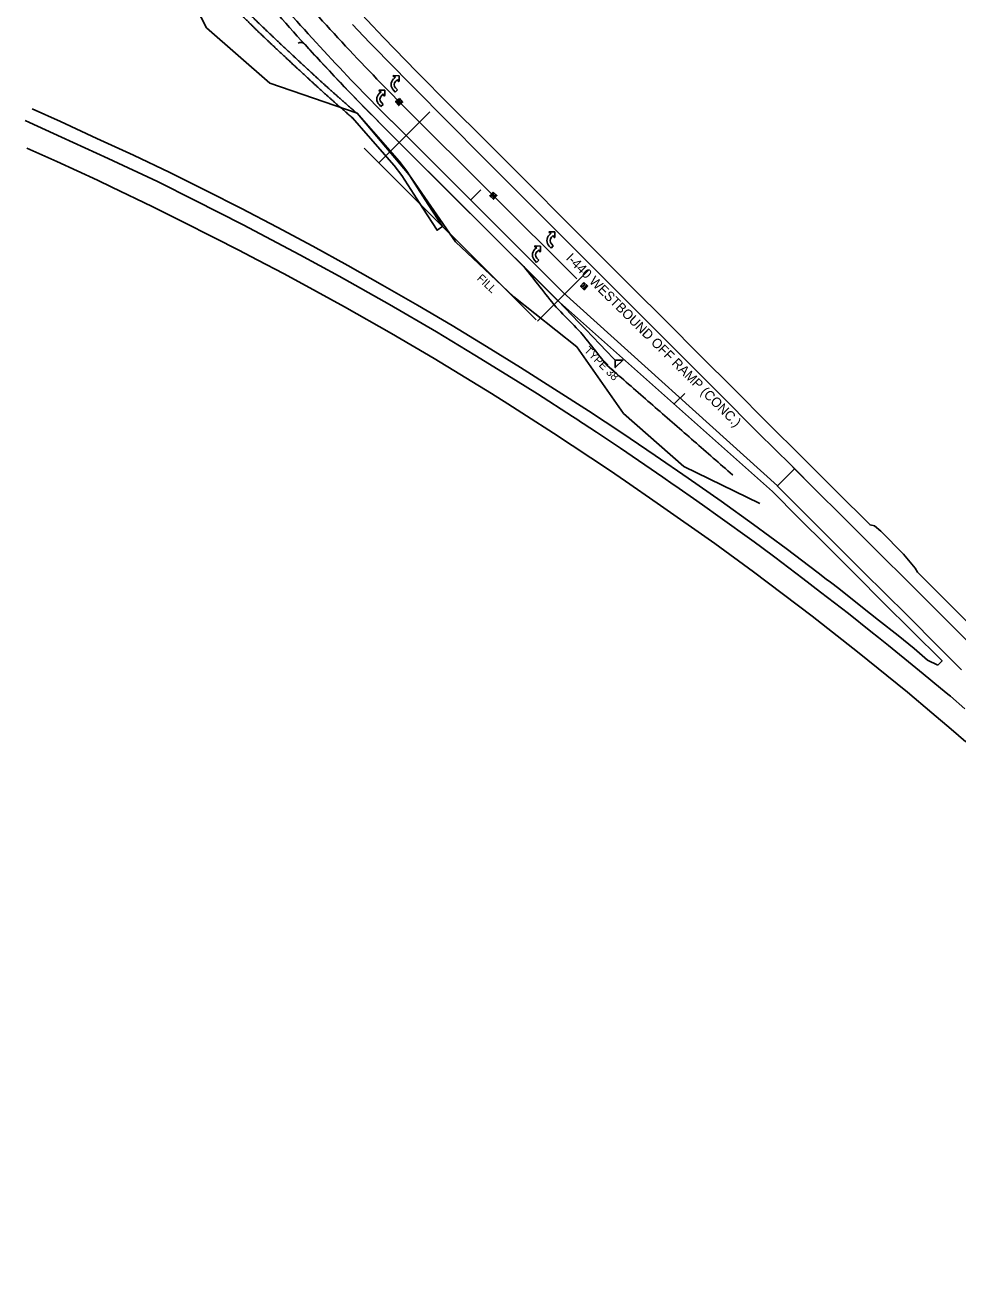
# Model space of a CAD drawing. Extents: x 1730210 to 1732101, y 650763 to 653427.
# Drawn here: x 1730478 to 1731060, y 651820 to 652609 of the extents above; entities that cross this region are included whole.
import ezdxf

# ---------------------------------------------------------------- set-up
doc = ezdxf.new("R2010")
doc.units = 0
for name, color, linetype in [('DESIGN - DRAINAGE - Special Ditches', 7, 'Continuous'), ('DESIGN - ROW - Slope Lines', 7, 'Continuous'), ('DESIGN - ROW - Slope Lines Text', 7, 'Continuous'), ('DESIGN - SCRATCH - User 1', 7, 'Continuous'), ('DESIGN - SCRATCH - User 2', 7, 'Continuous'), ('DESIGN - TRAFFIC CONTROL PERMANENT - Pavement Marking', 7, 'Continuous'), ('DESIGN - TRANSPORTATION - Edge of Traveled Way', 7, 'Continuous'), ('DESIGN - TRANSPORTATION - GR Special Slope Limit Lines', 7, 'Continuous'), ('DESIGN - TRANSPORTATION - Intersection Lines', 7, 'Continuous'), ('DESIGN - TRANSPORTATION - Roadside Barriers', 7, 'Continuous'), ('DESIGN - TRANSPORTATION - Shoulder Lines', 7, 'Continuous'), ('DESIGN - TRANSPORTATION - Text', 7, 'Continuous'), ('FUNCTIONAL - TRANSPORTATION - Preliminary Edge of Traveled Way', 7, 'Continuous'), ('SURVEY - DRAINAGE - Pipes and Culverts', 7, 'Continuous'), ('SURVEY - TRANSPORTATION - Features', 7, 'Continuous'), ('SURVEY - TRANSPORTATION - Roads', 7, 'Continuous'), ('SURVEY - TRANSPORTATION - Roads Text', 7, 'Continuous')]:
    doc.layers.add(name, color=color, linetype=linetype)

msp = doc.modelspace()

# ---------------------------------------------------------------- linework, layer by layer
at = {"layer": 'DESIGN - DRAINAGE - Special Ditches'}
msp.add_line((1730644.22, 652585.3), (1730644.22, 652585.3), dxfattribs=at)
for points in [[(1730610.11, 652623.81), (1730622.09, 652611.66), (1730634.46, 652599.88), (1730646.95, 652588.22)], [(1730607.26, 652621), (1730619.3, 652608.79), (1730631.71, 652596.98), (1730644.22, 652585.3)], [(1730644.22, 652585.3), (1730656.67, 652573.69), (1730669.31, 652562.29), (1730682.13, 652551.09)], [(1730646.95, 652588.22), (1730659.36, 652576.64), (1730671.97, 652565.27), (1730684.76, 652554.11)]]:
    msp.add_open_spline(points, degree=2, dxfattribs=at)
at = {"layer": 'DESIGN - ROW - Slope Lines'}
for p, q in [((1730565.43, 652657.01), (1730591, 652607.46)), ((1730591, 652607.46), (1730630.39, 652572.86)), ((1730630.39, 652572.86), (1730685.01, 652554.13)), ((1730685.01, 652554.13), (1730717.52, 652515.57)), ((1730717.52, 652515.57), (1730746.42, 652473.75)), ((1730746.42, 652473.75), (1730782.85, 652439.46)), ((1730782.85, 652439.46), (1730822.18, 652408.1)), ((1730822.18, 652408.1), (1730851.29, 652366.48)), ((1730851.29, 652366.48), (1730889.03, 652333.52)), ((1730889.03, 652333.52), (1730936.56, 652310.36))]:
    msp.add_line(p, q, dxfattribs=at)
at = {"layer": 'DESIGN - SCRATCH - User 1'}
for p, q in [((1730698.65, 652523.04), (1730730.44, 652554.89)), ((1730689.43, 652532.24), (1730796.78, 652425.11)), ((1730797.75, 652424.14), (1730829.53, 652456))]:
    msp.add_line(p, q, dxfattribs=at)
at = {"layer": 'DESIGN - SCRATCH - User 2'}
msp.add_lwpolyline([(1730682.18, 652609.42), (1730689.03, 652602.15), (1730693.2, 652597.85), (1730708.56, 652582.15), (1730715.58, 652575.04), (1730746.5, 652543.82), (1730759.18, 652531.06), (1730771.86, 652518.31), (1730793.02, 652497.08), (1730805.72, 652484.34), (1730831.15, 652458.88), (1730843.88, 652446.17), (1730863.71, 652426.41), (1730875.03, 652415.1), (1730899.04, 652391.04), (1730910.37, 652379.75), (1730935.76, 652354.33), (1730956.03, 652334.21), (1730971.98, 652318.3), (1730987.47, 652302.85), (1731007.33, 652283.11), (1731032.83, 652257.7), (1731045.57, 652244.98), (1731076.7, 652213.89)], dxfattribs=at)
at = {"layer": 'DESIGN - TRAFFIC CONTROL PERMANENT - Pavement Marking'}
for p, q in [((1730708.87, 652576.6), (1730707.71, 652575.46)), ((1730707.71, 652575.46), (1730708.87, 652576.6)), ((1730707.73, 652577.08), (1730708.87, 652576.6)), ((1730708.87, 652576.6), (1730707.73, 652577.08)), ((1730711.21, 652577.53), (1730707.83, 652577.55)), ((1730711.21, 652577.53), (1730707.83, 652577.55)), ((1730709.09, 652574.06), (1730710.25, 652575.2)), ((1730709.09, 652574.06), (1730710.25, 652575.2)), ((1730710.25, 652575.2), (1730710.71, 652574.06)), ((1730710.25, 652575.2), (1730710.71, 652574.06)), ((1730711.18, 652574.15), (1730711.21, 652577.53)), ((1730711.21, 652577.53), (1730711.18, 652574.15)), ((1730699.93, 652567.53), (1730698.77, 652566.39)), ((1730698.77, 652566.39), (1730699.93, 652567.53)), ((1730698.79, 652568.01), (1730699.93, 652567.53)), ((1730699.93, 652567.53), (1730698.79, 652568.01)), ((1730702.27, 652568.46), (1730698.89, 652568.48)), ((1730702.27, 652568.46), (1730698.89, 652568.48)), ((1730700.16, 652564.99), (1730701.31, 652566.13)), ((1730700.16, 652564.99), (1730701.31, 652566.13)), ((1730701.31, 652566.13), (1730701.77, 652564.99)), ((1730701.31, 652566.13), (1730701.77, 652564.99)), ((1730702.24, 652565.08), (1730702.27, 652568.46)), ((1730702.27, 652568.46), (1730702.24, 652565.08)), ((1730707.66, 652568.51), (1730708.84, 652567.31)), ((1730708.84, 652567.31), (1730707.66, 652568.51)), ((1730708.84, 652567.31), (1730710.24, 652568.69)), ((1730710.24, 652568.69), (1730708.84, 652567.31)), ((1730710.24, 652568.69), (1730709.06, 652569.89)), ((1730710.24, 652568.69), (1730709.06, 652569.89)), ((1730698.72, 652559.44), (1730699.9, 652558.24)), ((1730699.9, 652558.24), (1730698.72, 652559.44)), ((1730699.9, 652558.24), (1730701.3, 652559.62)), ((1730701.3, 652559.62), (1730699.9, 652558.24)), ((1730701.3, 652559.62), (1730700.12, 652560.82)), ((1730701.3, 652559.62), (1730700.12, 652560.82)), ((1730714.85, 652557.73), (1730822.21, 652450.59)), ((1730806.16, 652479.12), (1730805.01, 652477.99)), ((1730805.01, 652477.99), (1730806.16, 652479.12)), ((1730805.03, 652479.6), (1730806.16, 652479.12)), ((1730806.16, 652479.12), (1730805.03, 652479.6)), ((1730808.5, 652480.05), (1730805.12, 652480.07)), ((1730808.5, 652480.05), (1730805.12, 652480.07)), ((1730808.48, 652476.67), (1730808.5, 652480.05)), ((1730808.5, 652480.05), (1730808.48, 652476.67)), ((1730799.49, 652471.14), (1730796.11, 652471.17)), ((1730799.49, 652471.14), (1730796.11, 652471.17)), ((1730799.46, 652467.77), (1730799.49, 652471.14)), ((1730799.49, 652471.14), (1730799.46, 652467.77)), ((1730806.13, 652469.83), (1730807.53, 652471.22)), ((1730807.53, 652471.22), (1730806.13, 652469.83)), ((1730807.53, 652471.22), (1730806.36, 652472.41)), ((1730807.53, 652471.22), (1730806.36, 652472.41)), ((1730806.39, 652476.58), (1730807.54, 652477.72)), ((1730806.39, 652476.58), (1730807.54, 652477.72)), ((1730807.54, 652477.72), (1730808, 652476.58)), ((1730807.54, 652477.72), (1730808, 652476.58)), ((1730797.14, 652470.22), (1730795.99, 652469.08)), ((1730795.99, 652469.08), (1730797.14, 652470.22)), ((1730796.01, 652470.7), (1730797.14, 652470.22)), ((1730797.14, 652470.22), (1730796.01, 652470.7)), ((1730798.52, 652462.31), (1730797.34, 652463.51)), ((1730798.52, 652462.31), (1730797.34, 652463.51)), ((1730797.37, 652467.68), (1730798.52, 652468.82)), ((1730797.37, 652467.68), (1730798.52, 652468.82)), ((1730798.52, 652468.82), (1730798.99, 652467.68)), ((1730798.52, 652468.82), (1730798.99, 652467.68)), ((1730804.95, 652471.03), (1730806.13, 652469.83)), ((1730806.13, 652469.83), (1730804.95, 652471.03)), ((1730795.94, 652462.13), (1730797.12, 652460.93)), ((1730797.12, 652460.93), (1730795.94, 652462.13)), ((1730797.12, 652460.93), (1730798.52, 652462.31)), ((1730798.52, 652462.31), (1730797.12, 652460.93))]:
    msp.add_line(p, q, dxfattribs=at)
for points in [[(1730711.39, 652563.3), (1730708.98, 652561.26), (1730711.02, 652558.86), (1730713.42, 652560.9), (1730711.39, 652563.3)], [(1730711.39, 652563.3), (1730711.27, 652561.89), (1730710.36, 652561.11), (1730708.98, 652561.26)], [(1730713.42, 652560.9), (1730712.01, 652561.01), (1730711.1, 652560.23), (1730711.02, 652558.86)], [(1730770.01, 652504.8), (1730767.86, 652502.49), (1730770.16, 652500.34), (1730772.31, 652502.65), (1730770.01, 652504.8)], [(1730770.01, 652504.8), (1730770.06, 652503.38), (1730769.24, 652502.51), (1730767.86, 652502.49)], [(1730772.31, 652502.65), (1730770.9, 652502.6), (1730770.08, 652501.72), (1730770.16, 652500.34)], [(1730826.67, 652448.32), (1730824.52, 652446.01), (1730826.82, 652443.86), (1730828.97, 652446.17), (1730826.67, 652448.32)], [(1730826.67, 652448.32), (1730826.72, 652446.9), (1730825.9, 652446.03), (1730824.52, 652446.01)], [(1730828.97, 652446.17), (1730827.56, 652446.12), (1730826.74, 652445.24), (1730826.82, 652443.86)]]:
    msp.add_lwpolyline(points, dxfattribs=at)
for points in [[(1730711.27, 652561.89), (1730712.01, 652561.01), (1730711.1, 652560.23), (1730710.36, 652561.11)], [(1730770.06, 652503.38), (1730770.9, 652502.6), (1730770.08, 652501.72), (1730769.24, 652502.51)], [(1730826.72, 652446.9), (1730827.56, 652446.12), (1730826.74, 652445.24), (1730825.9, 652446.03)]]:
    msp.add_lwpolyline(points, close=True, dxfattribs=at)
for centre, radius, start, end in [((1731772.3, 653617.35), 1497, 220.70969, 225.05905), ((1730711.17, 652571.96), 4.92, 134.56927, 224.56927), ((1730711.17, 652571.96), 4.92, 134.56927, 224.56927), ((1730707.83, 652577.3), 0.246, 89.56927, 247.01753), ((1730707.83, 652577.3), 0.246, 89.56927, 247.01753), ((1730711.17, 652571.96), 2.95, 134.56927, 224.56927), ((1730711.17, 652571.96), 2.95, 134.56927, 224.56927), ((1730710.94, 652574.15), 0.246, 202.07611, 359.56927), ((1730710.94, 652574.15), 0.246, 202.07611, 359.56927), ((1730702.23, 652562.89), 4.92, 134.56927, 224.56927), ((1730702.23, 652562.89), 4.92, 134.56927, 224.56927), ((1730698.89, 652568.23), 0.246, 89.56927, 247.01753), ((1730698.89, 652568.23), 0.246, 89.56927, 247.01753), ((1730702.23, 652562.89), 2.95, 134.56927, 224.56927), ((1730702.23, 652562.89), 2.95, 134.56927, 224.56927), ((1730702, 652565.08), 0.246, 202.07611, 359.56927), ((1730702, 652565.08), 0.246, 202.07611, 359.56927), ((1730805.12, 652479.83), 0.246, 89.56927, 247.01753), ((1730805.12, 652479.83), 0.246, 89.56927, 247.01753), ((1730796.11, 652470.92), 0.246, 89.56927, 247.01753), ((1730796.11, 652470.92), 0.246, 89.56927, 247.01753), ((1730808.46, 652474.48), 4.92, 134.56927, 224.56927), ((1730808.46, 652474.48), 4.92, 134.56927, 224.56927), ((1730808.46, 652474.48), 2.95, 134.56927, 224.56927), ((1730808.46, 652474.48), 2.95, 134.56927, 224.56927), ((1730808.23, 652476.67), 0.246, 202.07611, 359.56927), ((1730808.23, 652476.67), 0.246, 202.07611, 359.56927), ((1730799.44, 652465.58), 4.92, 134.56927, 224.56927), ((1730799.44, 652465.58), 4.92, 134.56927, 224.56927), ((1730799.44, 652465.58), 2.95, 134.56927, 224.56927), ((1730799.44, 652465.58), 2.95, 134.56927, 224.56927), ((1730799.21, 652467.77), 0.246, 202.07611, 359.56927), ((1730799.21, 652467.77), 0.246, 202.07611, 359.56927)]:
    msp.add_arc(centre, radius, start, end, dxfattribs=at)
at = {"layer": 'DESIGN - TRANSPORTATION - Edge of Traveled Way'}
for p in [(1730706.38, 652549.23), (1730947.5, 652321.32)]:
    msp.add_line(p, (1730813.73, 652442.1), dxfattribs=at)
msp.add_lwpolyline([(1730682.18, 652609.42), (1730689.03, 652602.15), (1730693.2, 652597.85), (1730708.56, 652582.15), (1730715.58, 652575.04), (1730746.5, 652543.82), (1730759.18, 652531.06), (1730771.86, 652518.31), (1730793.02, 652497.08), (1730805.72, 652484.34), (1730831.15, 652458.88), (1730843.88, 652446.17), (1730863.71, 652426.41), (1730875.03, 652415.1), (1730899.04, 652391.04), (1730910.37, 652379.75), (1730935.76, 652354.33), (1730956.03, 652334.21), (1730958.2, 652332.05)], dxfattribs=at)
msp.add_arc((1731772.3, 653617.35), 1509, 220.70969, 225.05905, dxfattribs=at)
at = {"layer": 'DESIGN - TRANSPORTATION - GR Special Slope Limit Lines'}
msp.add_lwpolyline([(1730789.07, 652458.32), (1730790.32, 652456.74), (1730791.57, 652455.16), (1730792.82, 652453.58), (1730794.07, 652452), (1730795.32, 652450.42), (1730796.57, 652448.84), (1730797.82, 652447.26), (1730799.07, 652445.68), (1730800.32, 652444.11), (1730801.56, 652442.53), (1730802.81, 652440.95), (1730804.06, 652439.37), (1730805.31, 652437.79), (1730806.56, 652436.21), (1730807.81, 652434.63), (1730807.99, 652434.41), (1730809.38, 652432.97), (1730810.76, 652431.53), (1730812.15, 652430.08), (1730813.54, 652428.64), (1730814.93, 652427.2), (1730816.31, 652425.76), (1730817.7, 652424.32), (1730819.09, 652422.88), (1730820.47, 652421.44), (1730821.86, 652420), (1730823.25, 652418.56), (1730824.64, 652417.11), (1730825.33, 652416.39), (1730826.58, 652414.82), (1730827.84, 652413.24), (1730829.09, 652411.67), (1730830.34, 652410.09), (1730831.6, 652408.52), (1730832.85, 652406.94), (1730834.1, 652405.37), (1730835.36, 652403.79), (1730836.61, 652402.21), (1730837.86, 652400.64), (1730839.12, 652399.06), (1730840.37, 652397.49), (1730841, 652396.7), (1730842.51, 652395.38), (1730844.02, 652394.06), (1730845.53, 652392.74), (1730847.04, 652391.43), (1730848.54, 652390.11), (1730850.05, 652388.79), (1730851.56, 652387.47), (1730853.07, 652386.15), (1730854.58, 652384.83), (1730856.09, 652383.52), (1730857.6, 652382.2), (1730859.11, 652380.88), (1730860.62, 652379.56), (1730862.13, 652378.24), (1730863.64, 652376.92), (1730865.15, 652375.61), (1730866.66, 652374.29), (1730868.17, 652372.97), (1730869.68, 652371.65), (1730871.19, 652370.33), (1730872.7, 652369.01), (1730874.21, 652367.7), (1730875.72, 652366.38), (1730877.23, 652365.06), (1730878.74, 652363.74), (1730880.25, 652362.42), (1730881.76, 652361.1), (1730883.27, 652359.79), (1730884.78, 652358.47), (1730886.29, 652357.15), (1730887.8, 652355.83), (1730889.31, 652354.51), (1730890.82, 652353.19), (1730892.33, 652351.87), (1730893.84, 652350.56), (1730895.35, 652349.24), (1730896.86, 652347.92), (1730898.37, 652346.6), (1730899.88, 652345.28), (1730901.39, 652343.96), (1730902.9, 652342.65), (1730904.41, 652341.33), (1730905.92, 652340.01), (1730907.43, 652338.69), (1730908.94, 652337.37), (1730910.45, 652336.05), (1730911.96, 652334.74), (1730913.47, 652333.42), (1730914.98, 652332.1), (1730916.49, 652330.78), (1730918, 652329.46), (1730919.51, 652328.14), (1730919.56, 652328.1)], dxfattribs=at)
at = {"layer": 'DESIGN - TRANSPORTATION - Intersection Lines'}
msp.add_line((1730947.5, 652321.32), (1730958.2, 652332.05), dxfattribs=at)
at = {"layer": 'DESIGN - TRANSPORTATION - Roadside Barriers'}
for p, q in [((1730810.46, 652436.89), (1730702.14, 652544.98)), ((1730846.23, 652399.82), (1730845.19, 652400.9))]:
    msp.add_line(p, q, dxfattribs=at)
msp.add_lwpolyline([(1730845.19, 652400.9), (1730840.85, 652405.41), (1730836.52, 652409.91), (1730832.18, 652414.41), (1730827.85, 652418.92), (1730823.51, 652423.42), (1730810.5, 652436.93)], dxfattribs=at)
msp.add_lwpolyline([(1730846.23, 652399.82), (1730846.21, 652395.23), (1730850.97, 652399.8)], close=True, dxfattribs=at)
for centre, radius, start, end in [((1730649.95, 652595.31), 3, 35.18125, 125.18125), ((1731772.3, 653617.35), 1515, 222.33605, 225.05905)]:
    msp.add_arc(centre, radius, start, end, dxfattribs=at)
at = {"layer": 'DESIGN - TRANSPORTATION - Shoulder Lines'}
for p in [(1730702.14, 652544.98), (1730944.36, 652317.85)]:
    msp.add_line(p, (1730809.6, 652437.75), dxfattribs=at)
msp.add_arc((1731772.3, 653617.35), 1515, 220.70969, 225.05905, dxfattribs=at)
at = {"layer": 'FUNCTIONAL - TRANSPORTATION - Preliminary Edge of Traveled Way'}
for p, q in [((1730762.24, 652506.2), (1730755.88, 652499.83)), ((1730889.65, 652379.05), (1730883.29, 652372.68))]:
    msp.add_line(p, q, dxfattribs=at)
at = {"layer": 'SURVEY - DRAINAGE - Pipes and Culverts'}
for points in [[(1730682.21, 652551.17), (1730691.97, 652539.87), (1730708.12, 652521.5), (1730712.97, 652515.27), (1730725.95, 652494.83), (1730734.99, 652480.99), (1730736.55, 652482.03), (1730738.37, 652483.24)], [(1730684.91, 652554.24), (1730694.97, 652542.61), (1730711.29, 652524.04), (1730716.13, 652517.81), (1730729.33, 652497.08), (1730738.37, 652483.24)]]:
    msp.add_lwpolyline(points, dxfattribs=at)
at = {"layer": 'SURVEY - TRANSPORTATION - Features'}
for points in [[(1730680.98, 652623.04), (1730701.46, 652601.45), (1730722.34, 652580.03), (1730743.41, 652558.73), (1730764.61, 652537.57), (1730768.16, 652534.04), (1730793.21, 652508.89), (1730814.38, 652487.68), (1730835.6, 652466.49), (1730856.8, 652445.32), (1730878.03, 652424.11), (1730899.19, 652402.83), (1730920.41, 652381.64), (1730941.6, 652360.4), (1730962.88, 652339.27), (1730984.14, 652318.11), (1731005.4, 652296.96), (1731008.07, 652296.35)], [(1730482.13, 652556.78), (1730499.82, 652548.9), (1730522.53, 652538.36), (1730545.26, 652527.82), (1730568.01, 652517), (1730590.5, 652505.89), (1730612.79, 652494.56), (1730635.04, 652482.94), (1730657.24, 652471.12), (1730679.15, 652458.96), (1730700.91, 652446.66), (1730722.72, 652434.14), (1730744.45, 652421.45), (1730765.87, 652408.43), (1730787.1, 652395.25), (1730808.36, 652381.81), (1730829.42, 652368.2), (1730850.29, 652354.45), (1730871.15, 652340.34), (1730891.85, 652326.16), (1730912.26, 652311.72), (1730932.62, 652297.09), (1730952.92, 652282.17), (1730972.94, 652267.1), (1730977.98, 652263.09), (1730980.58, 652261.16), (1730985.79, 652257.15), (1731000.69, 652245.44)], [(1731047.73, 652209.41), (1731050.35, 652211.96), (1731031.53, 652230.73), (1731013.81, 652248.35), (1730996.17, 652266.06), (1730978.49, 652283.76), (1730960.75, 652301.37), (1730944.36, 652317.85)], [(1731008.07, 652296.35), (1731012.17, 652293.06), (1731026.29, 652278.76), (1731033.43, 652270.02)], [(1731033.43, 652270.02), (1731034.94, 652267.43), (1731048.46, 652253.94), (1731069.69, 652232.73), (1731090.91, 652211.51), (1731112.06, 652190.2), (1731133.28, 652168.97), (1731154.32, 652147.58), (1731175.37, 652126.2), (1731196.37, 652104.63), (1731217.28, 652083.07), (1731237.88, 652061.26), (1731258.4, 652039.18), (1731278.68, 652016.88), (1731284.06, 652009.86), (1731303.09, 651986.57), (1731322.55, 651963.65), (1731341.9, 651940.64), (1731361.11, 651917.48), (1731380.08, 651894.11), (1731398.72, 651870.57), (1731417.16, 651846.86), (1731435.47, 651822.97), (1731453.41, 651798.9)], [(1731000.69, 652245.44), (1731010.72, 652237.52), (1731022.93, 652227.87), (1731032.92, 652219.72), (1731041.23, 652212.43), (1731047.73, 652209.41)]]:
    msp.add_lwpolyline(points, dxfattribs=at)
at = {"layer": 'SURVEY - TRANSPORTATION - Roads'}
for points in [[(1730477.74, 652549.56), (1730480.41, 652548.34), (1730500.43, 652539.21), (1730529.49, 652525.81), (1730560.26, 652511.34), (1730583.53, 652499.76), (1730613.82, 652484.32), (1730649.22, 652465.7), (1730673.76, 652452.23), (1730705.2, 652434.69), (1730734.58, 652417.59), (1730758.51, 652403.05), (1730784.01, 652387.26), (1730797.56, 652378.75), (1730819.41, 652364.67), (1730822.77, 652362.5), (1730824.45, 652361.42), (1730826.12, 652360.32), (1730834.48, 652354.83), (1730849.52, 652344.94), (1730875.87, 652326.79), (1730882.45, 652322.24), (1730884.09, 652321.1), (1730897.16, 652311.88), (1730902.06, 652308.42), (1730910.23, 652302.65), (1730932.95, 652286.29), (1730937.81, 652282.78), (1730945.81, 652276.78), (1730963.37, 652263.53), (1730974.48, 652255.01), (1730991.85, 652241.52), (1731005.94, 652230.32), (1731010.62, 652226.57), (1731016.87, 652221.57), (1731021.55, 652217.83), (1731029.3, 652211.51), (1731038.59, 652203.91), (1731049.42, 652195.05), (1731054.02, 652191.19), (1731055.54, 652189.89), (1731064.63, 652182.06)], [(1731065.18, 652161.42), (1731056.1, 652169.25), (1731043.89, 652179.6), (1731028.64, 652192.53), (1730997.61, 652217.76), (1730969.27, 652239.95), (1730932.57, 652267.67), (1730908.36, 652285.39), (1730872.32, 652310.62), (1730852.59, 652324.29), (1730842.71, 652331.09), (1730807.69, 652354.26), (1730790.84, 652365.03), (1730779.05, 652372.57), (1730768.87, 652378.93), (1730733.06, 652400.86), (1730706.47, 652416.41), (1730677.11, 652433.11), (1730650.89, 652447.45), (1730639.01, 652453.88), (1730623.05, 652462.2), (1730610.64, 652468.67), (1730596.42, 652476.01), (1730574.98, 652486.79), (1730557.08, 652495.72), (1730531.87, 652507.9), (1730522.84, 652512.19), (1730497.39, 652523.87), (1730478.73, 652532.25)], [(1730958.2, 652332.05), (1730971.98, 652318.3), (1730987.47, 652302.85), (1731007.33, 652283.11), (1731032.83, 652257.7), (1731045.57, 652244.98), (1731076.7, 652213.89), (1731092.24, 652198.32)], [(1731062.56, 652206.46), (1731042.76, 652226.26), (1731034.27, 652234.74), (1731025.77, 652243.21), (1731017.24, 652251.66), (1730998.78, 652269.96), (1730976.37, 652292.33), (1730961.86, 652306.79), (1730957.88, 652310.75), (1730953.65, 652315.01), (1730947.43, 652321.26)]]:
    msp.add_lwpolyline(points, dxfattribs=at)

# ---------------------------------------------------------------- texts
at = {"layer": 'DESIGN - ROW - Slope Lines Text'}
msp.add_text('FILL', height=5, rotation=316.73321, dxfattribs=at).set_placement((1730759.5, 652450.45))
at = {"layer": 'DESIGN - TRANSPORTATION - Text'}
msp.add_text('TYPE 38', height=5, rotation=315.05905, dxfattribs=at).set_placement((1730826.41, 652405.51))
at = {"layer": 'SURVEY - TRANSPORTATION - Roads Text'}
msp.add_text('I-440 WESTBOUND OFF RAMP (CONC.)', height=6, rotation=315.19949, dxfattribs=at).set_placement((1730814.98, 652463.12))

doc.saveas('drawing.dxf')
